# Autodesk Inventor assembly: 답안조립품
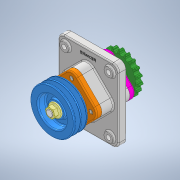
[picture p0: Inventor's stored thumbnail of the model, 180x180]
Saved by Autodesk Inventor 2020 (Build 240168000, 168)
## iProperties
Created: 2021-07
Part Number: 답안조립품
Document SubType Name: Assembly
Designer: Owner
Author: Owner
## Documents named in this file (16)
- C:\Users\Owner\Desktop\710707V1002\답안조립품.iam
- C:\Users\Owner\Desktop\710707V1002\본체.ipt
- C:\Users\Owner\Desktop\710707V1002\M16 너트.ipt
- C:\Users\Owner\Desktop\710707V1002\V-벨트풀리.ipt
- C:\Users\Owner\Desktop\710707V1002\멈춤나사 M4.ipt
- C:\Users\Owner\Desktop\710707V1002\베어링 6206.ipt
- C:\Users\Owner\Desktop\710707V1002\볼트 M6.ipt
- C:\Users\Owner\Desktop\710707V1002\부시.ipt
- C:\Users\Owner\Desktop\710707V1002\오일실 30x42x8.ipt
- C:\Users\Owner\Desktop\710707V1002\오일실 30x45x8.ipt
- C:\Users\Owner\Desktop\710707V1002\체인 스프로킷.ipt
- C:\Users\Owner\Desktop\710707V1002\축.ipt
- C:\Users\Owner\Desktop\710707V1002\커버A.ipt
- C:\Users\Owner\Desktop\710707V1002\커버B.ipt
- C:\Users\Owner\Desktop\710707V1002\키 6x6x18.ipt
- C:\Users\Owner\Desktop\710707V1002\키 6x6x20.ipt
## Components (3 placed, 2 different names)
1. M16 너트:1
2. V-벨트풀리:1
3. M16 너트:2
